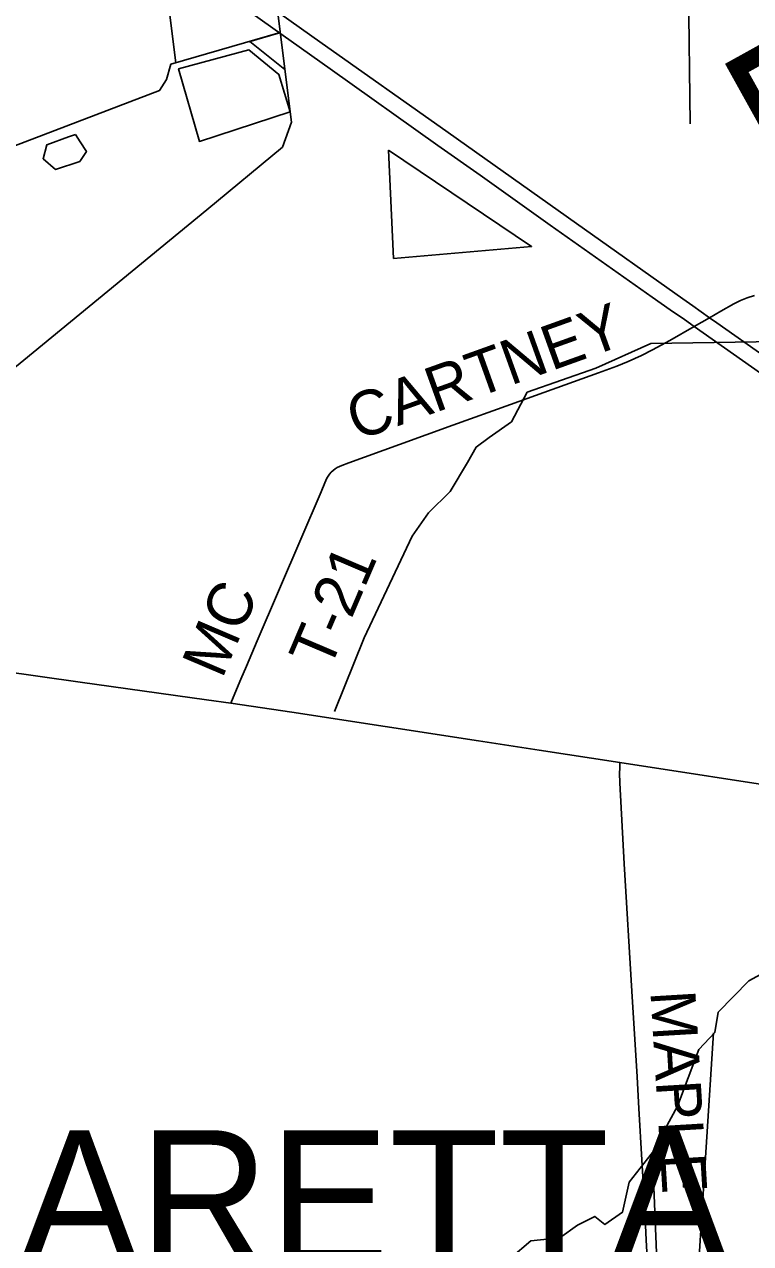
# Model space of a CAD drawing. Extents: x 0 to 34, y 0 to 22.
# Drawn here: x 7.056 to 7.515, y 15.545 to 16.318 of the extents above; entities that cross this region are included whole.
import ezdxf

# ---------------------------------------------------------------- set-up
doc = ezdxf.new("R2010")
doc.units = 0
for name, color, linetype in [('GM_X_County_Text', 7, 'Continuous'), ('GM_X_Minor_Lake', 7, 'Continuous'), ('GM_X_Minor_River', 7, 'Continuous'), ('GM_X_State_Route', 7, 'Continuous'), ('GM_X_Township_Road', 7, 'Continuous'), ('GM_X_Township_Road_Text', 7, 'Continuous'), ('GM_X_Township_Text', 7, 'Continuous'), ('GM_X_US_Route', 7, 'Continuous')]:
    doc.layers.add(name, color=color, linetype=linetype)

msp = doc.modelspace()

# ---------------------------------------------------------------- linework, layer by layer
at = {"layer": 'GM_X_Minor_Lake'}
for points in [[(7.08347, 16.2463), (7.06967, 16.24139), (7.06732, 16.23246), (7.07526, 16.22575), (7.09051, 16.23077), (7.09474, 16.2372), (7.0908, 16.24332), (7.08782, 16.24785)], [(7.08782, 16.24785), (7.08347, 16.2463)], [(7.28591, 16.23803), (7.2892, 16.16935), (7.37656, 16.17686), (7.31563, 16.21798)], [(7.31563, 16.21798), (7.28591, 16.23803)]]:
    msp.add_lwpolyline(points, dxfattribs=at)
at = {"layer": 'GM_X_Minor_River'}
for points in [[(7.27057, 16.45174), (7.28301, 16.33429), (7.37457, 16.36973), (7.39551, 16.37186), (7.40467, 16.37559), (7.4301, 16.36817), (7.44143, 16.33214), (7.46068, 16.33713), (7.40925, 16.50584), (7.438, 16.48318), (7.47593, 16.34062), (7.477, 16.25465)], [(7.21168, 16.3588), (7.2246, 16.25562), (7.21897, 16.23987), (7.17093, 16.20011), (7.05515, 16.10493), (7.04711, 16.09834), (7.02997, 16.04426), (7.02636, 15.91628)], [(7.1513, 16.29322), (7.14607, 16.33552), (7.16036, 16.33808)], [(6.97962, 16.20479), (7.04524, 16.22978), (7.0489, 16.23679), (7.04893, 16.2404), (7.14106, 16.27584), (7.14549, 16.28265), (7.14822, 16.29233), (7.21749, 16.31237)], [(7.19747, 16.30662), (7.21635, 16.3121)], [(7.19812, 16.30681), (7.22041, 16.28911)], [(7.22378, 16.26219), (7.16631, 16.2435), (7.15315, 16.28944), (7.19755, 16.30147), (7.21665, 16.28592), (7.22378, 16.26219)], [(7.72091, 16.26986), (7.67533, 16.29841), (7.60459, 16.17265), (7.59761, 16.12991), (7.58535, 16.11764), (7.452, 16.11542), (7.41726, 16.0999), (7.37378, 16.08463), (7.36375, 16.06588), (7.34979, 16.0559), (7.34138, 16.04988), (7.33598, 16.04022), (7.325, 16.02166), (7.31121, 16.00827), (7.30102, 15.99351), (7.27049, 15.92907), (7.25169, 15.88242)], [(8.01966, 15.97823), (8.01266, 15.97857), (8.00668, 15.96664), (7.99477, 15.95094), (7.96697, 15.92129), (7.9406, 15.90551), (7.75772, 15.84166), (7.67973, 15.81543), (7.67414, 15.80482), (7.62768, 15.79833), (7.61698, 15.79252), (7.60767, 15.79392), (7.57218, 15.77935), (7.55633, 15.74428), (7.5448, 15.72839), (7.51405, 15.71189), (7.49469, 15.69206), (7.49251, 15.67914), (7.48234, 15.66838), (7.46895, 15.63234), (7.45681, 15.61018), (7.45313, 15.60184), (7.4586, 15.46712)], [(7.46314, 15.23446), (7.49158, 15.67886)], [(7.45456, 15.60508), (7.43835, 15.58426), (7.43403, 15.56527), (7.42294, 15.55756), (7.41651, 15.56255), (7.40563, 15.55712), (7.39434, 15.54902), (7.37607, 15.54707), (7.36325, 15.53614), (7.34438, 15.53134), (7.14259, 15.53478), (6.97088, 15.54103)]]:
    msp.add_lwpolyline(points, dxfattribs=at)
at = {"layer": 'GM_X_State_Route'}
for points in [[(7.05472, 16.4249), (7.06735, 16.41888), (7.08403, 16.41052), (7.09641, 16.40401), (7.10862, 16.39718), (7.12068, 16.39009), (7.13655, 16.38029), (7.14963, 16.37189), (7.16379, 16.3623), (7.19814, 16.33814), (7.24253, 16.30662), (7.32379, 16.2491), (7.40505, 16.19158), (7.47226, 16.14384), (7.47858, 16.13931), (7.48912, 16.13182), (7.49379, 16.1285), (7.52438, 16.10708), (7.56117, 16.08099), (7.59541, 16.0568), (7.64248, 16.02354), (7.66775, 16.00591), (7.67995, 15.99725), (7.68291, 15.99506)], [(7.05531, 16.41863), (7.06769, 16.41212), (7.08129, 16.40461), (7.09339, 16.39759), (7.10532, 16.39028), (7.11835, 16.38181), (7.13118, 16.37306), (7.15024, 16.35964), (7.19961, 16.32456), (7.249, 16.2895), (7.31728, 16.24082), (7.34392, 16.22201), (7.38822, 16.19052), (7.45291, 16.14482), (7.46428, 16.13672), (7.47325, 16.13061), (7.47941, 16.12628), (7.5463, 16.07918), (7.55629, 16.07195), (7.58926, 16.04865), (7.59356, 16.0456), (7.59397, 16.04531)]]:
    msp.add_lwpolyline(points, dxfattribs=at)
at = {"layer": 'GM_X_Township_Road'}
for points in [[(7.196, 15.91109), (7.20285, 15.92716), (7.23051, 15.99147), (7.24326, 16.02154), (7.24559, 16.02732), (7.24696, 16.03017), (7.24778, 16.03154), (7.24871, 16.03283), (7.24976, 16.03403), (7.25094, 16.0351), (7.25222, 16.03606), (7.25357, 16.03689), (7.25642, 16.03829), (7.2608, 16.04), (7.29303, 16.05151), (7.32665, 16.06376), (7.36324, 16.07694), (7.4189, 16.09685), (7.43057, 16.10112), (7.43774, 16.10406), (7.44619, 16.10796), (7.4531, 16.11147), (7.46398, 16.11747), (7.47941, 16.12628), (7.48912, 16.13182), (7.49641, 16.13598), (7.50457, 16.14054), (7.50874, 16.14267), (7.51307, 16.14452), (7.51754, 16.14598)], [(7.1862, 15.88759), (7.18773, 15.89131), (7.19248, 15.90283), (7.196, 15.91109)], [(7.45389, 15.46131), (7.45104, 15.51211), (7.45038, 15.52451), (7.44907, 15.54776), (7.44868, 15.55685), (7.44826, 15.56586), (7.44443, 15.63094), (7.4433, 15.6511), (7.43999, 15.70537), (7.43514, 15.78602), (7.4324, 15.83722), (7.43228, 15.84345), (7.43234, 15.84657), (7.43241, 15.85013)]]:
    msp.add_lwpolyline(points, dxfattribs=at)
at = {"layer": 'GM_X_US_Route'}
msp.add_lwpolyline([(7.04006, 15.90817), (7.09085, 15.90102), (7.17088, 15.88979), (7.1862, 15.88759), (7.22472, 15.88203), (7.343, 15.86384), (7.38141, 15.85799), (7.43241, 15.85013), (7.5473, 15.83242), (7.57034, 15.82888), (7.57803, 15.82794), (7.58266, 15.82762), (7.58729, 15.82754), (7.59193, 15.82767), (7.5981, 15.82818), (7.64587, 15.83432), (7.68429, 15.83999), (7.70455, 15.84373), (7.71163, 15.84495)], dxfattribs=at)

# ---------------------------------------------------------------- texts
at = {"layer": 'GM_X_County_Text'}
msp.add_text('E', height=0.0947, rotation=299.00727, dxfattribs=at).set_placement((7.49394, 16.30173))
at = {"layer": 'GM_X_Township_Road_Text'}
for s, rotation, p in [('CARTNEY', 19.7779, (7.26596, 16.05376)), ('T-21', 66.89414, (7.2484, 15.90763)), ('MC', 66.9163, (7.18064, 15.90252)), ('MAPLE', 273.45047, (7.45171, 15.70505))]:
    msp.add_text(s, height=0.028409, rotation=rotation, dxfattribs=at).set_placement(p)
at = {"layer": 'GM_X_Township_Text'}
msp.add_text('MARGARETTA', height=0.085227, rotation=0.00001, dxfattribs=at).set_placement((6.71018, 15.53199))

doc.saveas('drawing.dxf')
